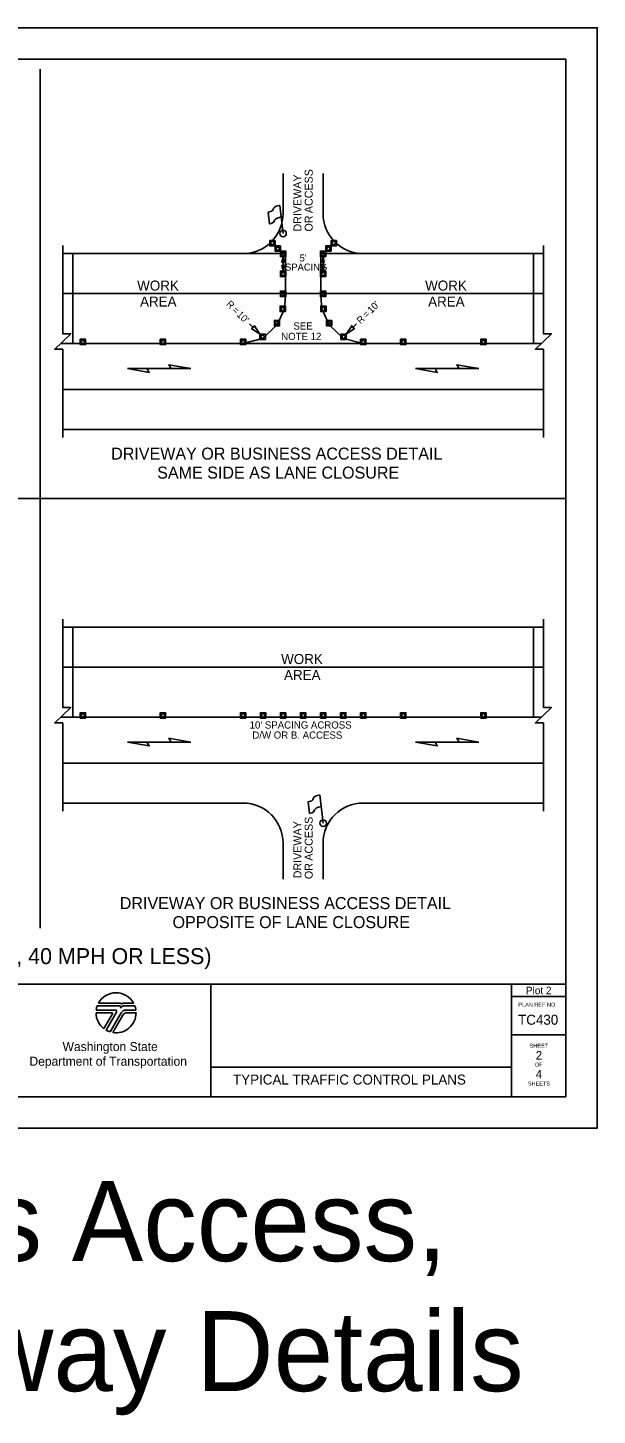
# Model space of a CAD drawing. Extents: x 99999.1 to 100095.7, y 99995 to 100010.7.
# Drawn here: x 100030.38 to 100036.06, y 99996.82 to 100010.69 of the extents above; entities that cross this region are included whole.
import ezdxf

# ---------------------------------------------------------------- set-up
doc = ezdxf.new("R2010")
doc.units = 0
for name, color, linetype in [('RD_ED_DrivewayEdge', 7, 'Continuous'), ('RD_ED_ShoulderPavedEdge', 7, 'Continuous'), ('RD_MK_LineEdgeWhite', 7, 'Continuous'), ('RD_MK_LineSkipCenter', 7, 'Continuous'), ('SH_DE_DetailHeading1Text', 7, 'Continuous'), ('SH_DE_DetailHeading2Text', 7, 'Continuous'), ('SH_GI_PlotLimits', 7, 'Continuous'), ('SH_GI_SheetBorder', 7, 'Continuous'), ('SH_GI_SheetLocationText', 7, 'Continuous'), ('SH_GI_SheetTextInCells', 7, 'Continuous'), ('SH_GI_TitleBlockText', 7, 'Continuous'), ('SH_GI_WSDOTLogo', 7, 'Continuous'), ('TR_WZ_FlaggingStation', 7, 'Continuous'), ('TR_WZ_TrafficCone', 7, 'Continuous'), ('TR_WZ_WorkAreaLabel', 7, 'Continuous'), ('TR_WZ_WorkZoneDetails', 7, 'Continuous'), ('TR_WZ_WorkZoneTextCurrent', 7, 'Continuous')]:
    doc.layers.add(name, color=color, linetype=linetype)

msp = doc.modelspace()

# ---------------------------------------------------------------- linework, layer by layer
at = {"layer": 'RD_ED_DrivewayEdge'}
for p, q in [((100032.925, 100008.83), (100032.925, 100009.23)), ((100033.325, 100008.83), (100033.325, 100009.23)), ((100032.925, 100002.536), (100032.925, 100002.176)), ((100033.325, 100002.536), (100033.325, 100002.176))]:
    msp.add_line(p, q, dxfattribs=at)
for centre, start, end in [((100032.525, 100008.83), 270, 0), ((100033.725, 100008.83), 180, 270), ((100032.525, 100002.536), 0, 90), ((100033.725, 100002.536), 90, 180)]:
    msp.add_arc(centre, 0.4, start, end, dxfattribs=at)
at = {"layer": 'RD_ED_ShoulderPavedEdge'}
for p, q in [((100030.725, 100008.43), (100032.525, 100008.43)), ((100033.725, 100008.43), (100035.525, 100008.43)), ((100030.725, 100006.67), (100035.525, 100006.67)), ((100030.725, 100004.696), (100035.525, 100004.696)), ((100030.725, 100002.936), (100032.525, 100002.936)), ((100033.725, 100002.936), (100035.525, 100002.936))]:
    msp.add_line(p, q, dxfattribs=at)
at = {"layer": 'RD_MK_LineEdgeWhite'}
for p, q in [((100030.725, 100008.03), (100035.525, 100008.03)), ((100030.725, 100007.07), (100035.525, 100007.07)), ((100030.725, 100004.296), (100035.525, 100004.296)), ((100030.725, 100003.336), (100035.525, 100003.336))]:
    msp.add_line(p, q, dxfattribs=at)
at = {"layer": 'RD_MK_LineSkipCenter'}
for points in [[(100035.504, 100007.53), (100030.704, 100007.53)], [(100035.504, 100003.796), (100030.704, 100003.796)]]:
    msp.add_lwpolyline(points, dxfattribs=at)
at = {"layer": 'SH_GI_PlotLimits'}
msp.add_lwpolyline([(100019.062, 99999.687), (100036.062, 99999.687), (100036.062, 100010.687), (100019.062, 100010.687)], close=True, dxfattribs=at)
at = {"layer": 'SH_GI_SheetBorder'}
for p, q in [((100020, 100010.375), (100035.75, 100010.375)), ((100035.75, 100010.375), (100035.75, 100000)), ((100020, 100001.126), (100035.75, 100001.126)), ((100032.205, 100001.126), (100032.205, 100000)), ((100035.208, 100001.126), (100035.208, 100000)), ((100035.208, 100001.001), (100035.75, 100001.001)), ((100035.208, 100000.618), (100035.75, 100000.618)), ((100032.205, 100000.295), (100035.208, 100000.295)), ((100020, 100000), (100035.75, 100000))]:
    msp.add_line(p, q, dxfattribs=at)
at = {"layer": 'SH_GI_WSDOTLogo'}
for p, q in [((100031.059, 100000.866), (100031.25, 100000.866)), ((100031.289, 100000.909), (100031.07, 100000.909)), ((100031.303, 100000.935), (100031.081, 100000.935)), ((100031.433, 100000.935), (100031.335, 100000.935)), ((100031.445, 100000.909), (100031.343, 100000.909)), ((100031.343, 100000.909), (100031.343, 100000.909)), ((100031.356, 100000.866), (100031.456, 100000.866)), ((100031.057, 100000.84), (100031.215, 100000.84)), ((100031.222, 100000.828), (100031.136, 100000.681)), ((100031.261, 100000.846), (100031.157, 100000.667)), ((100031.199, 100000.649), (100031.309, 100000.839)), ((100031.224, 100000.643), (100031.324, 100000.816)), ((100031.365, 100000.839), (100031.457, 100000.839))]:
    msp.add_line(p, q, dxfattribs=at)
for centre, radius, start, end in [((100031.257, 100000.84), 0.2, 28.4787, 151.532), ((100031.257, 100000.84), 0.2, 159.696, 172.5057), ((100031.25, 100000.853), 0.0131, 329.7683, 90), ((100031.289, 100000.895), 0.0148, 327.8418, 89.9985), ((100031.343, 100000.861), 0.0484, 89.9953, 147.8238), ((100031.303, 100000.926), 0.00903, 329.8742, 90.0033), ((100031.356, 100000.812), 0.0542, 90, 149.9974), ((100031.335, 100000.907), 0.0287, 90.0072, 148.1676), ((100031.257, 100000.84), 0.2, 7.4943, 20.2941), ((100031.257, 100000.84), 0.2, 179.9986, 232.8433), ((100031.215, 100000.832), 0.0082, 329.7436, 90), ((100031.257, 100000.84), 0.2, 260.5455, 359.8086), ((100031.365, 100000.792), 0.0476, 90, 150.0543), ((100031.257, 100000.84), 0.2, 239.7929, 253.0448)]:
    msp.add_arc(centre, radius, start, end, dxfattribs=at)
at = {"layer": 'TR_WZ_FlaggingStation'}
for p, q in [((100032.906, 100008.797), (100032.893, 100008.912)), ((100032.925, 100008.63), (100032.893, 100008.911)), ((100032.775, 100008.844), (100032.788, 100008.727)), ((100032.906, 100008.797), (100032.906, 100008.797)), ((100033.175, 100002.949), (100033.188, 100002.832)), ((100033.325, 100002.736), (100033.293, 100003.017)), ((100033.306, 100002.903), (100033.293, 100003.017)), ((100033.306, 100002.903), (100033.306, 100002.903))]:
    msp.add_line(p, q, dxfattribs=at)
for points in [[(100032.893, 100008.912), (100032.887, 100008.91), (100032.869, 100008.907), (100032.856, 100008.903), (100032.846, 100008.897), (100032.837, 100008.892), (100032.832, 100008.885), (100032.827, 100008.877), (100032.827, 100008.871), (100032.821, 100008.862), (100032.811, 100008.854), (100032.798, 100008.849), (100032.775, 100008.844)], [(100032.788, 100008.727), (100032.796, 100008.728), (100032.814, 100008.733), (100032.83, 100008.743), (100032.836, 100008.754), (100032.84, 100008.764), (100032.849, 100008.775), (100032.86, 100008.781), (100032.878, 100008.788), (100032.906, 100008.797)], [(100033.293, 100003.017), (100033.287, 100003.016), (100033.269, 100003.012), (100033.256, 100003.008), (100033.246, 100003.002), (100033.237, 100002.997), (100033.232, 100002.991), (100033.227, 100002.983), (100033.227, 100002.977), (100033.221, 100002.967), (100033.211, 100002.96), (100033.198, 100002.955), (100033.175, 100002.949)], [(100033.188, 100002.832), (100033.196, 100002.834), (100033.214, 100002.838), (100033.23, 100002.849), (100033.236, 100002.859), (100033.24, 100002.87), (100033.249, 100002.88), (100033.26, 100002.887), (100033.278, 100002.894), (100033.306, 100002.903)]]:
    msp.add_lwpolyline(points, dxfattribs=at)
for centre in [(100032.925, 100008.63), (100033.325, 100002.736)]:
    msp.add_circle(centre, 0.0325, dxfattribs=at)
at = {"layer": 'TR_WZ_TrafficCone'}
for points in [[(100032.845, 100008.56), (100032.845, 100008.507), (100032.792, 100008.507), (100032.792, 100008.56), (100032.845, 100008.56)], [(100032.792, 100008.56), (100032.792, 100008.507), (100032.845, 100008.507), (100032.845, 100008.56), (100032.792, 100008.56)], [(100032.898, 100008.507), (100032.898, 100008.454), (100032.845, 100008.454), (100032.845, 100008.507), (100032.898, 100008.507)], [(100032.845, 100008.507), (100032.845, 100008.454), (100032.898, 100008.454), (100032.898, 100008.507), (100032.845, 100008.507)], [(100033.352, 100008.507), (100033.352, 100008.454), (100033.405, 100008.454), (100033.405, 100008.507), (100033.352, 100008.507)], [(100033.405, 100008.507), (100033.405, 100008.454), (100033.352, 100008.454), (100033.352, 100008.507), (100033.405, 100008.507)], [(100033.405, 100008.56), (100033.405, 100008.507), (100033.458, 100008.507), (100033.458, 100008.56), (100033.405, 100008.56)], [(100033.458, 100008.56), (100033.458, 100008.507), (100033.405, 100008.507), (100033.405, 100008.56), (100033.458, 100008.56)], [(100032.898, 100008.454), (100032.952, 100008.454), (100032.952, 100008.4), (100032.898, 100008.4), (100032.898, 100008.454)], [(100032.898, 100008.4), (100032.952, 100008.4), (100032.952, 100008.454), (100032.898, 100008.454), (100032.898, 100008.4)], [(100033.352, 100008.454), (100033.298, 100008.454), (100033.298, 100008.4), (100033.352, 100008.4), (100033.352, 100008.454)], [(100033.352, 100008.4), (100033.298, 100008.4), (100033.298, 100008.454), (100033.352, 100008.454), (100033.352, 100008.4)], [(100032.898, 100008.254), (100032.952, 100008.254), (100032.952, 100008.2), (100032.898, 100008.2), (100032.898, 100008.254)], [(100032.898, 100008.2), (100032.952, 100008.2), (100032.952, 100008.254), (100032.898, 100008.254), (100032.898, 100008.2)], [(100033.352, 100008.254), (100033.298, 100008.254), (100033.298, 100008.2), (100033.352, 100008.2), (100033.352, 100008.254)], [(100033.352, 100008.2), (100033.298, 100008.2), (100033.298, 100008.254), (100033.352, 100008.254), (100033.352, 100008.2)], [(100032.898, 100008.054), (100032.952, 100008.054), (100032.952, 100008), (100032.898, 100008), (100032.898, 100008.054)], [(100032.898, 100008), (100032.952, 100008), (100032.952, 100008.054), (100032.898, 100008.054), (100032.898, 100008)], [(100033.352, 100008.054), (100033.298, 100008.054), (100033.298, 100008), (100033.352, 100008), (100033.352, 100008.054)], [(100033.352, 100008), (100033.298, 100008), (100033.298, 100008.054), (100033.352, 100008.054), (100033.352, 100008)], [(100032.896, 100007.904), (100032.949, 100007.904), (100032.949, 100007.85), (100032.896, 100007.85), (100032.896, 100007.904)], [(100032.896, 100007.85), (100032.949, 100007.85), (100032.949, 100007.904), (100032.896, 100007.904), (100032.896, 100007.85)], [(100033.354, 100007.904), (100033.301, 100007.904), (100033.301, 100007.85), (100033.354, 100007.85), (100033.354, 100007.904)], [(100033.354, 100007.85), (100033.301, 100007.85), (100033.301, 100007.904), (100033.354, 100007.904), (100033.354, 100007.85)], [(100032.838, 100007.762), (100032.891, 100007.762), (100032.891, 100007.708), (100032.838, 100007.708), (100032.838, 100007.762)], [(100032.838, 100007.708), (100032.891, 100007.708), (100032.891, 100007.762), (100032.838, 100007.762), (100032.838, 100007.708)], [(100033.412, 100007.762), (100033.359, 100007.762), (100033.359, 100007.708), (100033.412, 100007.708), (100033.412, 100007.762)], [(100033.412, 100007.708), (100033.359, 100007.708), (100033.359, 100007.762), (100033.412, 100007.762), (100033.412, 100007.708)], [(100030.899, 100007.574), (100030.952, 100007.574), (100030.952, 100007.52), (100030.899, 100007.52), (100030.899, 100007.574)], [(100030.899, 100007.52), (100030.952, 100007.52), (100030.952, 100007.574), (100030.899, 100007.574), (100030.899, 100007.52)], [(100031.699, 100007.574), (100031.752, 100007.574), (100031.752, 100007.52), (100031.699, 100007.52), (100031.699, 100007.574)], [(100031.699, 100007.52), (100031.752, 100007.52), (100031.752, 100007.574), (100031.699, 100007.574), (100031.699, 100007.52)], [(100032.499, 100007.574), (100032.552, 100007.574), (100032.552, 100007.52), (100032.499, 100007.52), (100032.499, 100007.574)], [(100032.499, 100007.52), (100032.552, 100007.52), (100032.552, 100007.574), (100032.499, 100007.574), (100032.499, 100007.52)], [(100032.694, 100007.625), (100032.748, 100007.625), (100032.748, 100007.571), (100032.694, 100007.571), (100032.694, 100007.625)], [(100032.694, 100007.571), (100032.748, 100007.571), (100032.748, 100007.625), (100032.694, 100007.625), (100032.694, 100007.571)], [(100033.556, 100007.625), (100033.502, 100007.625), (100033.502, 100007.571), (100033.556, 100007.571), (100033.556, 100007.625)], [(100033.556, 100007.571), (100033.502, 100007.571), (100033.502, 100007.625), (100033.556, 100007.625), (100033.556, 100007.571)], [(100033.699, 100007.574), (100033.752, 100007.574), (100033.752, 100007.52), (100033.699, 100007.52), (100033.699, 100007.574)], [(100033.699, 100007.52), (100033.752, 100007.52), (100033.752, 100007.574), (100033.699, 100007.574), (100033.699, 100007.52)], [(100034.099, 100007.574), (100034.152, 100007.574), (100034.152, 100007.52), (100034.099, 100007.52), (100034.099, 100007.574)], [(100034.099, 100007.52), (100034.152, 100007.52), (100034.152, 100007.574), (100034.099, 100007.574), (100034.099, 100007.52)], [(100034.899, 100007.574), (100034.952, 100007.574), (100034.952, 100007.52), (100034.899, 100007.52), (100034.899, 100007.574)], [(100034.899, 100007.52), (100034.952, 100007.52), (100034.952, 100007.574), (100034.899, 100007.574), (100034.899, 100007.52)], [(100030.899, 100003.839), (100030.952, 100003.839), (100030.952, 100003.786), (100030.899, 100003.786), (100030.899, 100003.839)], [(100030.899, 100003.786), (100030.952, 100003.786), (100030.952, 100003.839), (100030.899, 100003.839), (100030.899, 100003.786)], [(100031.699, 100003.839), (100031.752, 100003.839), (100031.752, 100003.786), (100031.699, 100003.786), (100031.699, 100003.839)], [(100031.699, 100003.786), (100031.752, 100003.786), (100031.752, 100003.839), (100031.699, 100003.839), (100031.699, 100003.786)], [(100032.499, 100003.839), (100032.552, 100003.839), (100032.552, 100003.786), (100032.499, 100003.786), (100032.499, 100003.839)], [(100032.499, 100003.786), (100032.552, 100003.786), (100032.552, 100003.839), (100032.499, 100003.839), (100032.499, 100003.786)], [(100032.699, 100003.839), (100032.752, 100003.839), (100032.752, 100003.786), (100032.699, 100003.786), (100032.699, 100003.839)], [(100032.699, 100003.786), (100032.752, 100003.786), (100032.752, 100003.839), (100032.699, 100003.839), (100032.699, 100003.786)], [(100032.899, 100003.839), (100032.952, 100003.839), (100032.952, 100003.786), (100032.899, 100003.786), (100032.899, 100003.839)], [(100032.899, 100003.786), (100032.952, 100003.786), (100032.952, 100003.839), (100032.899, 100003.839), (100032.899, 100003.786)], [(100033.099, 100003.839), (100033.152, 100003.839), (100033.152, 100003.786), (100033.099, 100003.786), (100033.099, 100003.839)], [(100033.099, 100003.786), (100033.152, 100003.786), (100033.152, 100003.839), (100033.099, 100003.839), (100033.099, 100003.786)], [(100033.299, 100003.839), (100033.352, 100003.839), (100033.352, 100003.786), (100033.299, 100003.786), (100033.299, 100003.839)], [(100033.299, 100003.786), (100033.352, 100003.786), (100033.352, 100003.839), (100033.299, 100003.839), (100033.299, 100003.786)], [(100033.499, 100003.839), (100033.552, 100003.839), (100033.552, 100003.786), (100033.499, 100003.786), (100033.499, 100003.839)], [(100033.499, 100003.786), (100033.552, 100003.786), (100033.552, 100003.839), (100033.499, 100003.839), (100033.499, 100003.786)], [(100033.699, 100003.839), (100033.752, 100003.839), (100033.752, 100003.786), (100033.699, 100003.786), (100033.699, 100003.839)], [(100033.699, 100003.786), (100033.752, 100003.786), (100033.752, 100003.839), (100033.699, 100003.839), (100033.699, 100003.786)], [(100034.099, 100003.839), (100034.152, 100003.839), (100034.152, 100003.786), (100034.099, 100003.786), (100034.099, 100003.839)], [(100034.099, 100003.786), (100034.152, 100003.786), (100034.152, 100003.839), (100034.099, 100003.839), (100034.099, 100003.786)], [(100034.899, 100003.839), (100034.952, 100003.839), (100034.952, 100003.786), (100034.899, 100003.786), (100034.899, 100003.839)], [(100034.899, 100003.786), (100034.952, 100003.786), (100034.952, 100003.839), (100034.899, 100003.839), (100034.899, 100003.786)]]:
    msp.add_lwpolyline(points, dxfattribs=at)
for centre in [(100032.818, 100008.534), (100032.872, 100008.48), (100033.378, 100008.48), (100033.432, 100008.534), (100032.925, 100008.427), (100033.325, 100008.427), (100032.925, 100008.227), (100033.325, 100008.227), (100032.925, 100008.027), (100033.325, 100008.027), (100032.922, 100007.877), (100033.328, 100007.877), (100032.865, 100007.735), (100033.385, 100007.735), (100030.926, 100007.547), (100031.726, 100007.547), (100032.526, 100007.547), (100032.721, 100007.598), (100033.529, 100007.598), (100033.726, 100007.547), (100034.126, 100007.547), (100034.926, 100007.547), (100030.926, 100003.813), (100031.726, 100003.813), (100032.526, 100003.813), (100032.726, 100003.813), (100032.926, 100003.813), (100033.126, 100003.813), (100033.326, 100003.813), (100033.526, 100003.813), (100033.726, 100003.813), (100034.126, 100003.813), (100034.926, 100003.813)]:
    msp.add_circle(centre, 0.0167, dxfattribs=at)
at = {"layer": 'TR_WZ_WorkZoneDetails'}
for p, q in [((100030.5, 100010.275), (100030.5, 100001.686)), ((100032.925, 100008.346), (100032.925, 100008.308)), ((100033.325, 100008.346), (100033.325, 100008.308)), ((100032.628, 100007.691), (100032.59, 100007.729)), ((100033.622, 100007.691), (100033.66, 100007.729)), ((100031.566, 100007.28), (100031.808, 100007.28)), ((100031.808, 100007.28), (100031.566, 100007.28)), ((100034.443, 100007.28), (100034.684, 100007.28)), ((100034.684, 100007.28), (100034.443, 100007.28)), ((100030.5, 100005.98), (100025.25, 100005.98)), ((100035.75, 100005.98), (100030.5, 100005.98)), ((100031.566, 100003.546), (100031.808, 100003.546)), ((100031.808, 100003.546), (100031.566, 100003.546)), ((100034.443, 100003.546), (100034.684, 100003.546)), ((100034.684, 100003.546), (100034.443, 100003.546))]:
    msp.add_line(p, q, dxfattribs=at)
for points in [[(100030.725, 100006.59), (100030.725, 100007.473), (100030.645, 100007.473), (100030.805, 100007.628), (100030.725, 100007.628), (100030.725, 100008.51)], [(100035.525, 100006.59), (100035.525, 100007.473), (100035.445, 100007.473), (100035.605, 100007.628), (100035.525, 100007.628), (100035.525, 100008.51)], [(100030.725, 100002.856), (100030.725, 100003.738), (100030.645, 100003.738), (100030.805, 100003.893), (100030.725, 100003.893), (100030.725, 100004.776)], [(100035.525, 100002.856), (100035.525, 100003.738), (100035.445, 100003.738), (100035.605, 100003.893), (100035.525, 100003.893), (100035.525, 100004.776)]]:
    msp.add_lwpolyline(points, dxfattribs=at)
for points in [[(100032.948, 100008.43), (100032.948, 100008.207), (100032.948, 100008.007), (100032.939, 100007.877), (100032.939, 100007.877), (100032.939, 100007.877), (100032.865, 100007.718), (100032.865, 100007.718), (100032.865, 100007.718), (100032.721, 100007.581), (100032.526, 100007.53), (100031.529, 100007.53), (100030.949, 100007.53), (100030.825, 100007.53), (100030.825, 100008.43)], [(100032.925, 100008.4), (100032.936, 100008.343), (100032.925, 100008.346), (100032.914, 100008.343)], [(100035.425, 100008.43), (100035.425, 100008.03), (100035.425, 100007.53), (100034.501, 100007.53), (100034.501, 100007.53), (100034.501, 100007.53), (100033.726, 100007.53), (100033.726, 100007.53), (100033.726, 100007.53), (100033.529, 100007.581), (100033.385, 100007.718), (100033.311, 100007.877), (100033.302, 100008.007), (100033.302, 100008.207), (100033.302, 100008.43)], [(100033.325, 100008.4), (100033.336, 100008.343), (100033.325, 100008.346), (100033.314, 100008.343)], [(100032.925, 100008.254), (100032.936, 100008.311), (100032.925, 100008.308), (100032.914, 100008.311)], [(100033.325, 100008.254), (100033.336, 100008.311), (100033.325, 100008.308), (100033.314, 100008.311)], [(100032.694, 100007.625), (100032.611, 100007.681), (100032.628, 100007.691), (100032.639, 100007.708)], [(100033.556, 100007.625), (100033.639, 100007.681), (100033.622, 100007.691), (100033.611, 100007.708)], [(100031.37, 100007.28), (100031.589, 100007.242), (100031.566, 100007.28)], [(100032.004, 100007.28), (100031.785, 100007.319), (100031.808, 100007.28)], [(100034.247, 100007.28), (100034.465, 100007.242), (100034.443, 100007.28)], [(100034.881, 100007.28), (100034.662, 100007.319), (100034.684, 100007.28)], [(100030.825, 100004.696), (100030.825, 100003.796), (100035.425, 100003.796), (100035.425, 100004.696)], [(100031.37, 100003.546), (100031.589, 100003.507), (100031.566, 100003.546)], [(100032.004, 100003.546), (100031.785, 100003.584), (100031.808, 100003.546)], [(100034.247, 100003.546), (100034.465, 100003.507), (100034.443, 100003.546)], [(100034.881, 100003.546), (100034.662, 100003.584), (100034.684, 100003.546)]]:
    msp.add_lwpolyline(points, close=True, dxfattribs=at)

# ---------------------------------------------------------------- texts
at = {"layer": 'SH_DE_DetailHeading1Text'}
msp.add_text('ALTERNATING 1-LANE, 2-WAY TRAFFIC: AFAD-CONTROLLED (HIGHWAYS, 40 MPH OR LESS)', height=0.16, rotation=360, dxfattribs=at).set_placement((100022.676, 100001.326))
at = {"layer": 'SH_DE_DetailHeading2Text'}
for s, p in [('DRIVEWAY OR BUSINESS ACCESS DETAIL', (100031.208, 100006.37)), ('SAME SIDE AS LANE CLOSURE', (100031.668, 100006.18)), ('DRIVEWAY OR BUSINESS ACCESS DETAIL', (100031.294, 100001.876)), ('OPPOSITE OF LANE CLOSURE', (100031.821, 100001.686))]:
    msp.add_text(s, height=0.12, rotation=360, dxfattribs=at).set_placement(p)
at = {"layer": 'SH_GI_SheetBorder'}
msp.add_text('PLAN REF NO', height=0.04003, dxfattribs=at).set_placement((100035.275, 100000.901))
at = {"layer": 'SH_GI_SheetLocationText'}
for s, height, p in [('Plot 2', 0.075, (100035.35, 100001.025)), ('Driveway, Business Access,', 0.8, (100021.184, 99998.357)), ('or Intersecting Roadway Details', 0.8, (100020.225, 99997.057))]:
    msp.add_text(s, height=height, dxfattribs=at).set_placement(p)
at = {"layer": 'SH_GI_SheetTextInCells'}
for s, height, p in [('Washington State', 0.09007, (100030.723, 100000.457)), ('SHEET', 0.04, (100035.388, 100000.49)), ('Department of Transportation', 0.09007, (100030.392, 100000.31)), ('OF', 0.04, (100035.441, 100000.301)), ('SHEETS', 0.04, (100035.37, 100000.112))]:
    msp.add_text(s, height=height, dxfattribs=at).set_placement(p)
at = {"layer": 'SH_GI_TitleBlockText'}
for s, height, p in [('TC430', 0.1, (100035.272, 100000.72)), ('2', 0.085, (100035.449, 100000.372)), ('TYPICAL TRAFFIC CONTROL PLANS', 0.1, (100032.425, 100000.122)), ('4', 0.085, (100035.449, 100000.184))]:
    msp.add_text(s, height=height, dxfattribs=at).set_placement(p)
at = {"layer": 'TR_WZ_WorkAreaLabel'}
for s, p in [('WORK', (100031.468, 100008.06)), ('WORK', (100034.344, 100008.06)), ('AREA', (100031.497, 100007.9)), ('AREA', (100034.374, 100007.9)), ('WORK', (100032.906, 100004.326)), ('AREA', (100032.935, 100004.166))]:
    msp.add_text(s, height=0.1, dxfattribs=at).set_placement(p)
at = {"layer": 'TR_WZ_WorkZoneTextCurrent'}
for s, height, rotation, p in [('DRIVEWAY', 0.08, 90, (100033.109, 100008.65)), ('ACCESS', 0.08, 90, (100033.221, 100008.834)), ('OR', 0.08, 90, (100033.221, 100008.65)), ('R', 0.07, 315, (100032.351, 100007.919)), ("10'", 0.07, 45, (100033.808, 100007.827)), ('=', 0.07, 315, (100032.41, 100007.859)), ("10'", 0.07, 315, (100032.457, 100007.813)), ('R', 0.07, 45, (100033.701, 100007.721)), ('=', 0.07, 45, (100033.761, 100007.78)), ('ACCESS', 0.08, 90, (100033.221, 100002.36)), ('DRIVEWAY', 0.08, 90, (100033.109, 100002.184)), ('OR', 0.08, 90, (100033.221, 100002.176))]:
    msp.add_text(s, height=height, rotation=rotation, dxfattribs=at).set_placement(p)
for s, height, p in [("5'", 0.07, (100033.09, 100008.351)), ('SPACING', 0.07, (100032.945, 100008.26)), ('SEE', 0.072, (100033.028, 100007.67)), ('NOTE 12', 0.072, (100032.906, 100007.566)), ("10' SPACING ACROSS", 0.072, (100032.591, 100003.681)), ('D/W OR B. ACCESS', 0.072, (100032.618, 100003.58))]:
    msp.add_text(s, height=height, dxfattribs=at).set_placement(p)

doc.saveas('drawing.dxf')
